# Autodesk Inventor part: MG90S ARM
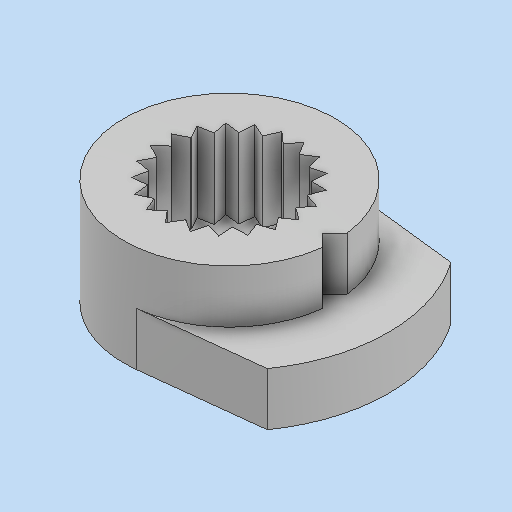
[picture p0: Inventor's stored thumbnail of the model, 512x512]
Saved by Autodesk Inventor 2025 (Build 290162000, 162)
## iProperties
Created: 2024-10
Part Number: MG90S ARM
Material: Steel
Document SubType Name: Modeling
Designer: Ryzen5700u
Density: 7.85 g/cm^3
Appearance: Default
Sending System: Autodesk Translation Framework v13.20.0.188
Preprocessor: ST-DEVELOPER v20
Title: MG90S ARM.step
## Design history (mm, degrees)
feature "Body2"
sketch "Schizzo1"
  geometry: L1 (-11.15, 0)-(-10.678, 0.472) reference; L2 (-10.678, -0.472)-(-11.15, 0) reference; L3 (-14.195, -3.974)-(0.265, -2.335) reference; L4 (0.265, 2.335)-(-14.195, 3.974) reference; C1 r 1.25 at (-14.65, 0) reference; C2 r 6 at (-14.65, 0); C3 r 1 at (0, 0) reference; A1 r 4 centre (-14.65, 0) between (-10.678, 0.472) and (-14.195, 3.974) reference; A2 r 4 centre (-14.65, 0) between (-14.195, -3.974) and (-10.678, -0.472) reference; A3 r 2.35 centre (0, 0) between (0.265, -2.335) and (0.265, 2.335) reference; 3 further points
  constraints: 1 centre point, 1 coincident
  dimensions: "d0" = 12 diameter of C2
extrude "Estrusione1" cut sketch "Schizzo1" extent not by distance; stored distance "d1" = 0; taper "d2" = 0 deg
node "Solido1"
node "Linea chiusa proiettata1"
